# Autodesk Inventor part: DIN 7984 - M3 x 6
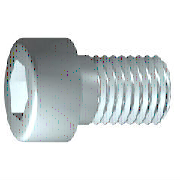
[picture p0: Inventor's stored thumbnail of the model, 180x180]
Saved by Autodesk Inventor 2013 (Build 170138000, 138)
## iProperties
IsCustomPart: 0
Created: 2012-02
Part Number: DIN 7984 - M3 x 6
Material: Stahl, weich
Description: Zylinderkopfschraube
Document SubType Name: Modeling
Standard: DIN 7984
Designer: rYan
Standard Revision: 1985
Standards Organization: DIN
Language: de-DE
Size Designation: M3 x 6
Categories: <MemberInstance><Categories><Category DisplayName="Verbindungselemente" InternalName="e4da775c-781d-43d5-af7c-5136215cf5a6" Mnemonic="FSTN"><Category DisplayNam
Density: 7.86 g/cm^3
Mass: 0.653232 g
Surface Area: 1.45477 cm^2
Volume: 0.0831084 cm^3
Author: rYan
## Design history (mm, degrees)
sketch "Skizze1"
  geometry: L1 (0.167, 0)-(6, 0); L2 (6, 0)-(6, 1.5); L3 (6, 1.5)-(1.5, 1.5); L4 (1.5, 1.5)-(1.193, 1.5); L5 (1.193, 1.5)-(0, 1.5); L6 (0, 1.5)-(0, 2.75); L7 (0, 2.75)-(-2, 2.75); L8 (-2, 2.75)-(-2, 1.155); L9 (-2, 1.155)-(-0.5, 1.155); L10 (-0.5, 1.155)-(0.167, 0); L11 (-3.6, 0)-(7.6, 0) reference; L12 (0, -0.55)-(0, 3.3) reference; L13 (1.5, 1.5)-(0, 1.5)
  constraints: 22 end point, 6 parallel, 2 collinear, 2 perpendicular, 1 horizontal, 1 point on line
  dimensions: "d1" = 4.5 distance from line of L3.end L2 (= GEL); "d2" = 0.30683 distance of L4.end L3.end (computed from GAL); "d3" = 2 distance between parallel lines of L8 L6 (= KOH); "d4" = 1.5 distance of L8.end L9.end (= INTI); "d5" = 60 deg angle of L10 L1; "d6" = 3 diameter of L3 L1 (= GD); "d7" = 3 diameter of L5 L1 (= BDM); "d8" = 2.3094 diameter of L9 L1 (= 1.1547 x SW); "d9" = 5.5 diameter of L7 L1 (= KOD); "d26" = 6 distance between parallel lines of L12 L2 (= NLG)
revolve "Körper" sketch "Skizze1" stored, may be unused: angle "d10" = 90 deg
sketch "Skizze2"
  geometry: L1 (0, -3.85)-(0, 3.85) reference; L2 (-3.85, 0)-(3.85, 0) reference; L3 (1.155, 0)-(0.577, -1); L4 (0.577, -1)-(-0.577, -1); L5 (-0.577, -1)-(-1.155, 0); L6 (-1.155, 0)-(-0.577, 1); L7 (-0.577, 1)-(0.577, 1); L8 (0.577, 1)-(1.155, 0); 2 further points
  constraints: 12 end point, 1 coincident, 1 horizontal alignment, 1 point on line, 12 other
extrude "Loch" join sketch "Skizze2" stored distance "d11" = 10; taper "d12" = 0 deg
workplane "Work Plane1"
fillet "Fillet2" dims "d30" = 0.1 (= R)
body "Solid1"
fillet "Rundung1" dims "d17" = 0.3 (= RR)
feature "Gewinde" dims "d13" = 4.5 (= GEL), "d14" = 0
chamfer "Fase1" distance "d15" = 0.30673 (= -0.5 x SPD + 0.5 x GD); stored, may be unused: second distance "d16" = 0.30673 (= GUL), angle "d27" = 45 deg
other parameters: "GD" = 3 (= NND) [user parameter; used in 2 equation terms], "NLG" = 6 [user parameter; used in 1 equation term], "GEL" = 4.5 [user parameter; used in 2 equation terms], "KOD" = 5.5 [user parameter; used in 1 equation term], "KOH" = 2 [user parameter; used in 1 equation term], "INTI" = 1.5 [user parameter; used in 1 equation term], "GAL" = 0.30673 (= 0.61345 x PTC) [user parameter; used in 1 equation term], "GUL" = 0.30673 (= 0.61345 x PTC) [user parameter; used in 1 equation term], "BDM" = 3 (= NND) [user parameter; used in 1 equation term], "SW" = 2 [user parameter; used in 2 equation terms], "RR" = 0.3 [user parameter; used in 1 equation term], "SPD" = 2.38655 (= NND - 1.2269 x PTC) [user parameter; used in 1 equation term], "d19" = 0, "d28" = 0, "d29" = 0, "R" = 0.1 [user parameter; used in 1 equation term], "TOA" = 30 deg [user parameter], "GD1" = 2.38655 (= THREADDIA - 1.2269 x PTC) [user parameter], "THREADDIA" = 3 [user parameter; used in 1 equation term], "FAWI" = 45 deg [user parameter], "ANG" = 120 deg [user parameter], "PTC" = 0.5 [user parameter; used in 5 equation terms], "NND" = 3 [user parameter; used in 3 equation terms], "E0" = 2.31 (= 1.155 x SW) [user parameter]
